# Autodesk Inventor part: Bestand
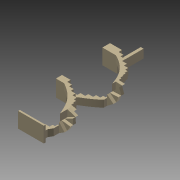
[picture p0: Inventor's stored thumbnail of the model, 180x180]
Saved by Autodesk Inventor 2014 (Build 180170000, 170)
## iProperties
Created: 2013-09
Part Number: Bestand
Material: Generisch
Document SubType Name: Modeling
Designer: Stefan Tammegger
Density: 1 g/cm^3
Appearance: Vorgabe
Mass: 1.57495e+06 g
Surface Area: 233340 cm^2
Volume: 1.57495e+06 cm^3
Author: Stefan Tammegger
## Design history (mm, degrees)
sketch "Skizze1"
  geometry: L1 (0, 0)-(1500, 0); L2 (1500, 0)-(1500, -100); L3 (1500, -100)-(0, -100); L4 (0, -100)-(0, 0)
  constraints: 8 end point, 2 parallel, 1 horizontal, 1 perpendicular
  dimensions: "d0" = 1500 distance of L2.end L3.end; "d1" = 100 distance of L1.end L2.end
extrude "Extrusion1" new body sketch "Skizze1" distance "d2" = 400; taper "d3" = 0 deg
sketch "Skizze2"
  geometry: L1 (0, 0)-(1500, 0) reference; L2 (1500, 0)-(1500, -100) reference; L3 (400, 0)-(400, 180); L4 (400, 180)-(680, 180); L5 (680, 180)-(680, 350); L6 (680, 350)-(960, 350); L7 (960, 350)-(960, 525); L8 (960, 525)-(1210, 525); L9 (1210, 525)-(1210, 705); L10 (1210, 705)-(1350, 705); L11 (1350, 705)-(1350, 870); L12 (1350, 870)-(1420, 870); L13 (400, 0)-(1290, 0); L14 (1290, 0)-(1290, 335); L15 (1420, 870)-(1420, 560); L16 (1290, 335)-(1420, 560)
  constraints: 28 end point, 8 parallel, 4 perpendicular, 2 point on line
  dimensions: "d4" = 180 distance of L3.start L3.end; "d5" = 280 distance of L3.end L4.end; "d6" = 400 distance from line of L3 L1.start; "d7" = 170 distance of L4.end L5.end; "d8" = 280 distance of L5.end L6.end; "d9" = 175 distance of L6.end L7.end; "d10" = 250 distance of L7.end L8.end; "d11" = 180 distance of L8.end L9.end; "d12" = 140 distance of L9.end L10.end; "d13" = 165 distance of L10.end L11.end; "d14" = 70 distance of L12.end L11.end; "d15" = 890 distance of L3.start L13.end; "d16" = 335 distance of L13.end L14.end; "d17" = 310 distance of L12.end L15.end
extrude "Extrusion2" new body sketch "Skizze2" distance "d20" = 400; taper "d21" = 0 deg
workplane "Arbeitsebene1"
sketch "Skizze3"
  geometry: L1 (0, 0)-(1500, 0) reference; L2 (400, 180)-(680, 180) reference; L3 (680, 350)-(960, 350) reference; L4 (960, 525)-(1210, 525) reference; L5 (1210, 525)-(1210, 705) reference; L6 (1210, 705)-(1350, 705) reference; L7 (1350, 705)-(1350, 870) reference; L8 (1350, 870)-(1420, 870) reference; L9 (1420, 870)-(1420, 560) reference; L10 (-776.238, 2940)-(5222.158, 2940); L11 (28, 2940)-(28, 2740); L12 (28, 2740)-(308, 2740); L13 (308, 2740)-(308, 2570); L14 (308, 2570)-(585, 2570); L15 (585, 2570)-(585, 2395); L16 (585, 2395)-(860, 2395); L17 (860, 2395)-(860, 2220); L18 (860, 2220)-(1110, 2220); L19 (1110, 2220)-(1110, 2045); L20 (1110, 2045)-(1250, 2045); L21 (1250, 2045)-(1250, 1870); L22 (1250, 1870)-(1305, 1870); L23 (1305, 1870)-(1305, 1695); L24 (1305, 1695)-(1360, 1695); L25 (1360, 1695)-(1360, 1525); L26 (1360, 1525)-(1420, 1525); L27 (1420, 1525)-(1420, 2664.653); L28 (1420, 1525)-(1420, 925); L29 (28, 2940)-(-472, 2940); L30 (-472, 2940)-(-472, 2581.023); L31 (-472, 2581.023)-(8, 2581.023); L32 (1420, 925)-(1137.455, 1605.397); L33 (1137.455, 1605.397)-(905.038, 2029.236); L34 (905.038, 2029.236)-(405.99, 2354.697); L35 (405.99, 2354.697)-(8, 2581.023)
  constraints: 44 end point, 11 perpendicular, 9 parallel, 2 collinear, 2 point on line, 3 other
  dimensions: "d23" = 2940 distance between parallel lines of L1 L10; "d24" = 200 distance of L11.start L11.end; "d25" = 280 distance of L11.end L12.end; "d26" = 170 distance of L12.end L13.end; "d27" = 277 distance of L13.end L14.end; "d28" = 175 distance of L14.end L15.end; "d29" = 275 distance of L15.end L16.end; "d30" = 175 distance of L16.end L17.end; "d31" = 250 distance of L17.end L18.end; "d32" = 175 distance of L18.end L19.end; "d33" = 140 distance of L19.end L20.end; "d34" = 175 distance of L20.end L21.end; "d35" = 55 distance of L21.end L22.end; "d36" = 175 distance of L22.end L23.end; "d37" = 55 distance of L23.end L24.end; "d38" = 170 distance of L24.end L25.end; "d39" = 60 distance of L25.end L26.end; "d40" = 600 distance of L26.end L28.end; "d41" = 500 distance of L11.start L29.end; "d46" = 280 distance of L14.end L34.end; "d47" = 280 distance of L18.end L33.end; "d48" = 190 distance of L23.end L32.end; "d49" = 300 distance from line of L31.end L13
extrude "Extrusion3" join sketch "Skizze3" distance "d50" = 400; taper "d51" = 0 deg
sketch "Skizze5"
  geometry: L1 (10, -165)-(70, -165) reference; L2 (-45, -165)-(10, -165) reference; L3 (70, 400)-(70, -165); L4 (70, -165)-(390.323, 200); L5 (390.323, 200)-(70, 400); 1 further point
  constraints: 6 end point, 1 perpendicular
extrude "Extrusion4" join sketch "Skizze5" distance "d53" = 163.75; taper "d54" = 0 deg
sketch "Skizze6"
  geometry: L1 (70, -165)-(390.323, 200); L2 (390.323, 200)-(567.635, -95.246); L3 (567.635, -95.246)-(70, -165); 1 further point
  constraints: 6 end point
extrude "Extrusion5" join sketch "Skizze6" distance "d55" = 163.75; taper "d56" = 0 deg
sketch "Skizze7"
  geometry: L1 (70, -165)-(567.635, -95.246) reference; L2 (70, -165)-(567.635, -95.246); L3 (567.635, -95.246)-(546.081, -409.71); L4 (546.081, -409.71)-(70, -165); 1 further point
  constraints: 6 end point, 1 collinear
extrude "Extrusion6" join sketch "Skizze7" distance "d57" = 163.75; taper "d58" = 0 deg
sketch "Skizze8"
  geometry: L1 (70, -165)-(546.081, -409.71) reference; L2 (70, -165)-(70, -565) reference; L3 (70, -165)-(546.081, -409.71); L4 (70, -565)-(546.081, -409.71); L5 (70, -565)-(70, -165); 1 further point
  constraints: 6 end point, 1 collinear
extrude "Extrusion7" join sketch "Skizze8" distance "d59" = 163.75; taper "d60" = 0 deg
sketch "Skizze9"
  geometry: L1 (55, 0)-(55, -400) reference; L2 (115, -400)-(591.081, -244.71) reference; L3 (55, 0)-(328.6, -330.327); L4 (328.6, -330.327)-(55, -400); 1 further point
  constraints: 4 end point, 1 point on line
extrude "Extrusion8" join sketch "Skizze9" stored distance "d61" = 163.75; taper "d62" = 0 deg
sketch "Skizze10"
  geometry: L1 (-1420, 1525)-(-1420, 1361.25) reference; L2 (472, 2581.023)-(472, 2940) reference; L3 (472, 2940)-(-28, 2940) reference; L4 (472, 2940)-(-125, 2940); L5 (-125, 2940)-(-125, 2581.023); L6 (-125, 2581.023)-(472, 2581.023); L7 (472, 2940)-(472, 2581.023); 1 further point
  constraints: 8 end point, 1 collinear, 1 parallel, 1 perpendicular, 1 point on line
  dimensions: "d63" = 1295 distance between parallel lines of L5 L1
extrude "Extrusion9" join sketch "Skizze10" distance "d64" = 165; taper "d65" = 0 deg
workplane "Arbeitsebene2"
sketch "Skizze11"
  geometry: L1 (472, 2940)-(-125, 2940) reference; L2 (-125, 2940)-(-125, 2581.023) reference; L3 (-125, 2940)-(-420, 2940); L4 (-420, 2940)-(-420, 3125); L5 (-420, 3125)-(-700, 3125); L6 (-700, 3125)-(-700, 3305); L7 (-700, 3305)-(-980, 3305); L8 (-980, 3305)-(-980, 3480); L9 (-980, 3480)-(-1225, 3480); L10 (-1225, 3480)-(-1225, 3650); L11 (-1225, 3650)-(-1365, 3650); L12 (-1365, 3650)-(-1365, 3830); L13 (-1365, 3830)-(-1440, 3830); L14 (-1440, 3830)-(-1440, 3480); L15 (-125, 2940)-(-125, 2581.023); 3 further points
  constraints: 26 end point, 7 parallel, 5 perpendicular, 1 collinear, 1 point on line, 4 other
  dimensions: "d67" = 295 distance of L1.end L3.end; "d68" = 185 distance of L3.end L4.end; "d69" = 280 distance of L4.end L5.end; "d70" = 180 distance of L5.end L6.end; "d71" = 280 distance of L6.end L7.end; "d72" = 175 distance of L7.end L8.end; "d73" = 245 distance of L8.end L9.end; "d74" = 170 distance of L9.end L10.end; "d75" = 140 distance of L10.end L11.end; "d76" = 180 distance of L11.end L12.end; "d77" = 75 distance of L12.end L13.end; "d78" = 320 distance of L4.end point (-618.385, 2873.915); "d79" = 305 distance of L8.end point (-1151.981, 3228.112)
extrude "Extrusion10" join sketch "Skizze11" distance "d80" = 400; taper "d81" = 0 deg
sketch "Skizze12"
  geometry: L1 (472, 2581.023)-(472, 2940) reference; L2 (472, 2940)-(-125, 2940) reference; L3 (-125, 2940)-(-125, 2581.023) reference; L4 (-125, 2581.023)-(472, 2581.023) reference; 1 further point
extrude "Extrusion11" join sketch "Skizze12" distance "d82" = 400; taper "d83" = 0 deg
workplane "Arbeitsebene3"
sketch "Skizze13"
  geometry: L1 (1440, 3830)-(1440, 3480) reference; L2 (1365, 3830)-(1440, 3830) reference; L3 (1365, 3650)-(1365, 3830) reference; L4 (1225, 3650)-(1365, 3650) reference; L5 (1225, 3480)-(1225, 3650) reference; L6 (-472, 2940)-(420, 2940) reference; L7 (28, 2740)-(28, 2940) reference; L8 (125, 2940)-(125, 2740) reference; L9 (-472, 4325)-(2891.853, 4325); L10 (1440, 4510)-(1370, 4510); L11 (1370, 4510)-(1370, 4690); L12 (1370, 4690)-(1315, 4690); L13 (1315, 4690)-(1315, 4865); L14 (1315, 4865)-(1255, 4865); L15 (1255, 4865)-(1255, 5045); L16 (1255, 5045)-(1112, 5045); L17 (1112, 5045)-(1112, 5225); L18 (1112, 5225)-(862, 5225); L19 (862, 5225)-(862, 5400); L20 (862, 5400)-(582, 5400); L21 (582, 5400)-(582, 5585); L22 (582, 5585)-(302, 5585); L23 (302, 5585)-(302, 5750); L24 (302, 5750)-(22, 5750); L25 (22, 5750)-(22, 5950); L26 (22, 5950)-(-678, 5950); L27 (-678, 5950)-(-678, 5505); L28 (-678, 5505)-(107, 5505); L29 (1440, 4510)-(1440, 4722.035); L30 (1440, 4510)-(1440, 3950); 3 further points
  constraints: 44 end point, 9 parallel, 6 perpendicular, 2 collinear, 4 other
  dimensions: "d86" = 1385 distance between parallel lines of L6 L9; "d88" = 70 distance of L10.start L10.end; "d89" = 180 distance of L10.end L11.end; "d90" = 55 distance of L11.end L12.end; "d91" = 175 distance of L12.end L13.end; "d92" = 60 distance of L13.end L14.end; "d93" = 180 distance of L14.end L15.end; "d94" = 143 distance of L15.end L16.end; "d95" = 180 distance of L16.end L17.end; "d96" = 250 distance of L17.end L18.end; "d97" = 175 distance of L18.end L19.end; "d98" = 280 distance of L19.end L20.end; "d99" = 185 distance of L20.end L21.end; "d100" = 280 distance of L21.end L22.end; "d101" = 165 distance of L22.end L23.end; "d102" = 280 distance of L23.end L24.end; "d103" = 200 distance of L24.end L25.end; "d105" = 445 distance of L26.end L27.end; "d106" = 700 distance of L25.end L26.end; "d107" = 195 distance from line of L28.end L23; "d110" = 185 distance between parallel lines of L9 L10; "d111" = 560 distance of L10.start L30.end; "d112" = 280 distance of point (1102.463, 4682.714) L13.end; "d113" = 310 distance of L19.end point (672.233, 5154.871)
extrude "Extrusion12" join sketch "Skizze13" distance "d114" = 400; taper "d115" = 0 deg
sketch "Skizze14"
  geometry: L1 (-1440, 3950)-(-1440, 4510) reference; L2 (678, 5505)-(-107, 5505) reference; L3 (-22, 5750)-(-22, 5950) reference; L4 (-1370, 4510)-(-1370, 4690) reference; L5 (-185, 5505)-(-185, 7050); L6 (-185, 7050)-(-22, 7050); L7 (-22, 7050)-(-22, 5505); L8 (-185, 5505)-(-22, 5505); 1 further point
  constraints: 8 end point, 2 collinear, 2 perpendicular, 1 parallel, 1 point on line
  dimensions: "d119" = 1545 distance of L5.start L5.end; "d123" = 1255 distance between parallel lines of L5 L1
extrude "Extrusion13" join sketch "Skizze14" distance "d124" = 500; taper "d125" = 0 deg
sketch "Skizze15"
  geometry: L1 (-22, 5750)-(-22, 5505) reference; L2 (678, 5505)-(-22, 5505) reference; L3 (678, 5950)-(678, 5505) reference; L4 (-22, 5950)-(678, 5950) reference; L5 (-22, 5750)-(-22, 5950) reference; 1 further point
extrude "Extrusion14" join sketch "Skizze15" stored distance "d126" = 500; taper "d127" = 0 deg
sketch "Skizze16"
  geometry: L1 (0, 0)-(1500, 0) reference; L2 (0, -100)-(0, 0) reference; L3 (1500, -100)-(0, -100) reference; L4 (1500, 0)-(1500, -100) reference
extrude "Extrusion15" join sketch "Skizze16" distance "d128" = 500; taper "d129" = 0 deg
sketch "Skizze18"
  geometry: L1 (5, -170)-(-50, -170) reference; L2 (75, -170)-(5, -170) reference; L3 (75, 400)-(75, -170); L4 (75, -170)-(443.777, 124.048); L5 (443.777, 124.048)-(75, 400); 1 further point
  constraints: 6 end point, 1 perpendicular, 1 point on line
extrude "Extrusion17" join sketch "Skizze18" distance "d132" = 170; taper "d133" = 0 deg
sketch "Skizze19"
  geometry: L1 (75, -170)-(443.777, 124.048) reference; L2 (75, -170)-(443.777, 124.048); L3 (443.777, 124.048)-(566.048, -191.09); L4 (566.048, -191.09)-(75, -170); 1 further point
  constraints: 6 end point, 1 collinear
extrude "Extrusion18" join sketch "Skizze19" distance "d134" = 170; taper "d135" = 0 deg
sketch "Skizze20"
  geometry: L1 (75, -170)-(566.048, -191.09) reference; L2 (75, -170)-(566.048, -191.09); L3 (566.048, -191.09)-(443.777, -550.487); L4 (443.777, -550.487)-(75, -170); 1 further point
  constraints: 6 end point, 1 collinear
extrude "Extrusion19" join sketch "Skizze20" distance "d136" = 170; taper "d137" = 0 deg
sketch "Skizze21"
  geometry: L1 (75, -170)-(443.777, -550.487) reference; L2 (75, -170)-(75, -570) reference; L3 (75, -170)-(75, -570); L4 (75, -570)-(443.777, -550.487); L5 (443.777, -550.487)-(75, -170); 1 further point
  constraints: 6 end point, 2 collinear
extrude "Extrusion20" join sketch "Skizze21" distance "d138" = 170; taper "d139" = 0 deg
node "Volumenkörper1"
node "Volumenkörper2"
feature "䂁"
other parameters: "d22" = 165, "d66" = 0
